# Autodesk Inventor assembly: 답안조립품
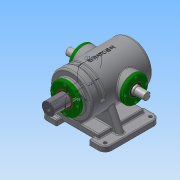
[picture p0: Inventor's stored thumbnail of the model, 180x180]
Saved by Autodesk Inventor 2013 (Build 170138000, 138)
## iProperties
Created: 2018-06
Part Number: 답안조립품
Document SubType Name: Assembly
Designer: Administrator
Mass: 8560.47 g
Surface Area: 4294.68 cm^2
Volume: 2307.06 cm^3
Density: 3.71055 g/cm^3
Author: Administrator
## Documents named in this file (13)
- C:\Users\Administrator\Desktop\380628V1005\답안조립품.iam
- C:\Users\Administrator\Desktop\380628V1005\본체.ipt
- C:\Users\Administrator\Desktop\380628V1005\가변스프링.ipt
- C:\Users\Administrator\Desktop\380628V1005\베어링 6205.ipt
- 베어링 6205.ipt
- C:\Users\Administrator\Desktop\380628V1005\볼트 M4.ipt
- C:\Users\Administrator\Desktop\380628V1005\부시.ipt
- C:\Users\Administrator\Desktop\380628V1005\슬라이드 커버.ipt
- C:\Users\Administrator\Desktop\380628V1005\슬라이드.ipt
- C:\Users\Administrator\Desktop\380628V1005\오일실.ipt
- 오일실.ipt
- C:\Users\Administrator\Desktop\380628V1005\축 커버.ipt
- C:\Users\Administrator\Desktop\380628V1005\편심축.ipt
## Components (1 placed, 1 different names)
1. 가변스프링:1
